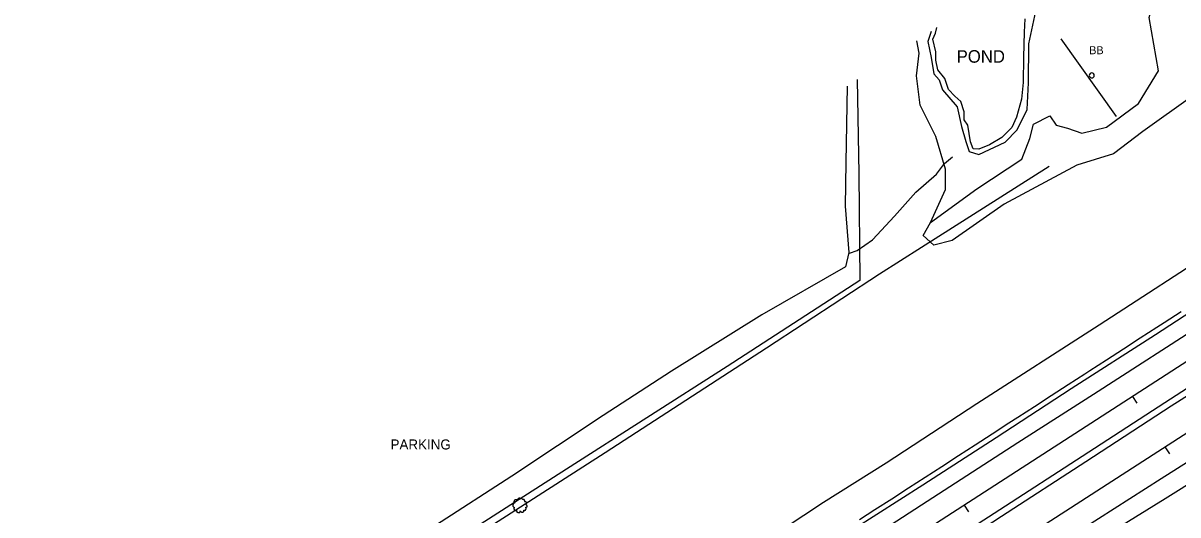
# Model space of a CAD drawing. Extents: x 1901471 to 1963503, y 756461 to 799997.
# Drawn here: x 1920585 to 1921162, y 767828 to 768073 of the extents above; entities that cross this region are included whole.
import ezdxf

# ---------------------------------------------------------------- set-up
doc = ezdxf.new("R2010")
doc.units = 0
for name, color, linetype in [('Default', 7, 'Continuous'), ('RD_DTM_BkLn1', 7, 'Continuous'), ('RD_EX_Bldg', 7, 'Continuous'), ('RD_EX_Fence_Other', 7, 'Continuous'), ('RD_EX_H2O', 7, 'Continuous'), ('RD_EX_Road', 7, 'Continuous'), ('RD_EX_VEG', 7, 'Continuous'), ('RD_HC_Cl', 7, 'Continuous'), ('RD_HC_Data_Tic', 7, 'Continuous')]:
    doc.layers.add(name, color=color, linetype=linetype)

# ---------------------------------------------------------------- blocks, each defined once
blk = doc.blocks.new('T2')
at = {"layer": 'RD_EX_VEG'}
for points in [[(0.05233333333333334, 7.213166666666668), (-0.24750000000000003, 7.238166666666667), (-0.5723333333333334, 7.138166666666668), (-0.8222500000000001, 7.038250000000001), (-1.0471666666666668, 6.963250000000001), (-1.2720833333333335, 6.863250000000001), (-1.5719166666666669, 6.688416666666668), (-1.7968333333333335, 6.488416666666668), (-1.9218333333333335, 6.2385833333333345), (-1.9718333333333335, 6.013666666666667), (-2.0217500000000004, 5.738833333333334), (-2.0217500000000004, 5.563833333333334), (-2.146666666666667, 5.538833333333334), (-2.296666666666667, 5.563833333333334), (-2.5465000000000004, 5.638833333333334), (-2.796416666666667, 5.638833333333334), (-3.0463333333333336, 5.638833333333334), (-3.3961666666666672, 5.613833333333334), (-3.7460000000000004, 5.613833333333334), (-4.020833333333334, 5.563833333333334), (-4.345750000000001, 5.513916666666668), (-4.720583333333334, 5.389000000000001), (-5.0704166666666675, 5.264000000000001), (-5.37025, 5.014083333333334), (-5.620166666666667, 4.539333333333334), (-5.745166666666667, 4.189500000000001), (-5.895083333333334, 3.9395833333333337), (-5.745166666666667, 3.489833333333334), (-5.570166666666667, 3.139916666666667), (-5.545250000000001, 2.9400000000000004), (-5.470250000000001, 2.5152500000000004), (-5.37025, 2.2903333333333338), (-5.245333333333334, 2.0903333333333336), (-5.320250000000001, 2.065416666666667), (-5.695166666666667, 2.015416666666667), (-5.995000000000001, 1.9155000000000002), (-6.419833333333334, 1.6905833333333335), (-6.644750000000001, 1.465666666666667), (-6.744750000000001, 1.1407500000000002), (-6.769666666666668, 0.7909166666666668), (-6.869583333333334, 0.5910833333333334), (-6.944583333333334, 0.3161666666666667), (-6.969583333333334, 0.2411666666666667), (-7.019583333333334, -0.08366666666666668), (-6.9195833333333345, -0.5335000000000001), (-6.894583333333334, -0.8833333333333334), (-6.769666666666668, -1.1082500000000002), (-6.619750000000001, -1.2830833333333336), (-6.444833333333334, -1.5330000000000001), (-6.045000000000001, -1.7579166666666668), (-5.7201666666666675, -1.8579166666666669), (-5.520250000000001, -1.8828333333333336), (-5.695166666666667, -2.382666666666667), (-5.745166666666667, -2.7325000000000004), (-5.870083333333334, -3.132333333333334), (-5.870083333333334, -3.2072500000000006), (-5.920000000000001, -3.682083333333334), (-5.770166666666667, -4.007000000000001), (-5.695166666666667, -4.38175), (-5.520250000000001, -4.606666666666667), (-5.245333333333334, -4.906583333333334), (-4.9205000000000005, -5.131416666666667), (-4.420666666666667, -5.256416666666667), (-4.020833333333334, -5.231416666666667), (-3.4460833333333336, -5.056500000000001), (-3.1962500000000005, -4.9815000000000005), (-3.2212500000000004, -5.156416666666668), (-3.1962500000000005, -5.531333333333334), (-3.1962500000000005, -5.956083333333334), (-3.0463333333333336, -6.280916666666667), (-2.946333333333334, -6.555833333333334), (-2.796416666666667, -6.805750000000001), (-2.4715000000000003, -7.030583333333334), (-2.07175, -7.1055833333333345), (-1.6469166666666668, -7.2555000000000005), (-1.1970833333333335, -7.330500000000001), (-0.6973333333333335, -7.355500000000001), (-0.09758333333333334, -7.205583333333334), (0.17725000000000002, -7.080583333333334), (0.27725000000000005, -6.905666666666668), (0.47716666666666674, -6.530833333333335), (0.4271666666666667, -6.3059166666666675), (0.4521666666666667, -5.706166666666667), (0.5520833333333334, -5.881166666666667), (0.7270833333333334, -6.231000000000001), (1.2268333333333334, -6.530833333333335), (1.626666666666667, -6.705750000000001), (2.101416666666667, -6.8557500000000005), (2.4013333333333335, -6.930666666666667), (2.8760833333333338, -6.8557500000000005), (3.2510000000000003, -6.780750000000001), (3.6257500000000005, -6.655750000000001), (3.9256666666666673, -6.380916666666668), (4.100583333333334, -6.106000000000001), (4.1505833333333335, -5.831166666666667), (4.2255, -5.456333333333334), (4.275500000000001, -5.281416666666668)], [(4.275500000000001, -5.281416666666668), (4.200583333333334, -5.106416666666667), (4.1505833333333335, -4.856583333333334), (4.2255, -4.881583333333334), (4.4004166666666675, -4.931583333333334), (4.675333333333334, -5.056500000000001), (4.900250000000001, -5.131416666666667), (5.225083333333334, -5.106416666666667), (5.500000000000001, -5.006500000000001), (5.949750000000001, -4.731583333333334), (6.224666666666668, -4.256833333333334), (6.499500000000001, -3.8570000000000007), (6.5745000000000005, -3.5321666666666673), (6.524500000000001, -3.3072500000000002), (6.499500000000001, -2.8075000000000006), (6.299583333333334, -2.5575833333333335), (6.249583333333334, -2.432666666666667), (6.1496666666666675, -2.0328333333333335), (6.224666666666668, -1.9828333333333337), (6.499500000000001, -1.9328333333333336), (6.874333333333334, -1.8079166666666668), (7.149250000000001, -1.6830000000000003), (7.374166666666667, -1.5080000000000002), (7.449083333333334, -1.2830833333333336), (7.424166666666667, -0.8833333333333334), (7.4740833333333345, -0.48350000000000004), (7.399166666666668, -0.3335), (7.299166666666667, -0.1836666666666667), (7.224166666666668, 0.016333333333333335), (7.074250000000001, 0.16616666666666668), (6.974333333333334, 0.3161666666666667), (6.874333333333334, 0.41608333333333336), (6.749416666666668, 0.5660833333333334), (6.5745000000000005, 0.6910000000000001), (6.424583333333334, 0.7410000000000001), (6.374583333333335, 0.8909166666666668), (6.524500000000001, 1.0908333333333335), (6.5745000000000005, 1.1907500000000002), (6.599416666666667, 1.4156666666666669), (6.824416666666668, 1.7655000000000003), (6.874333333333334, 2.1653333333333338), (6.824416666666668, 2.590166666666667), (6.774416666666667, 2.8650833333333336), (6.624416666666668, 3.139916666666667), (6.424583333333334, 3.3898333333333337), (6.299583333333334, 3.5647500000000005), (6.124666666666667, 3.689666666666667), (5.799833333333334, 3.814666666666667), (5.549916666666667, 3.864583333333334), (5.200083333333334, 3.864583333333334), (5.000166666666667, 3.9145833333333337), (5.025166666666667, 3.964583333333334), (5.025166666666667, 4.1145000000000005), (5.025166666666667, 4.389416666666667), (4.950166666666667, 4.839166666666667), (4.800250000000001, 5.339), (4.800250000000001, 5.364000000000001), (4.7002500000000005, 5.613833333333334), (4.475416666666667, 5.813750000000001), (4.3005, 5.913666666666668), (4.100583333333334, 6.038666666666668), (3.850666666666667, 6.063666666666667), (3.5508333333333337, 6.063666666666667), (3.2759166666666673, 6.013666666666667), (3.0760000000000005, 5.913666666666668), (2.9010833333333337, 5.788750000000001), (2.8260833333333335, 5.938666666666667), (2.726166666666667, 6.2385833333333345), (2.676166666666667, 6.3885000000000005), (2.52625, 6.563416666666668), (2.301416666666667, 6.7633333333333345), (1.8515000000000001, 6.888250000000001), (1.2268333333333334, 6.813333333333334), (0.9269166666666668, 6.613416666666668), (0.7770000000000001, 6.438500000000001), (0.7270833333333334, 6.563416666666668), (0.5270833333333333, 6.7633333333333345), (0.4271666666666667, 6.938250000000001), (0.25225000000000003, 7.063250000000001), (0.10233333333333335, 7.163166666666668), (0.0023333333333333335, 7.213166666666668)]]:
    blk.add_spline(points, degree=3, dxfattribs=at)
blk = doc.blocks.new('SIGNPOST')
at = {"layer": 'Default'}
for centre, start, end in [((7.776250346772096e-18, 0), 90.00000000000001, 270), ((-7.776250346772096e-18, 0), 270, 90)]:
    blk.add_arc(centre, 0.12700000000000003, start, end, dxfattribs=at)

msp = doc.modelspace()

# ---------------------------------------------------------------- linework, layer by layer
at = {"layer": 'RD_DTM_BkLn1'}
for points in [[(1921010.6918800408, 767830.4550401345), (1921019.0928901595, 767835.876703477), (1921027.493900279, 767841.2983668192), (1921035.8949103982, 767846.7200301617), (1921044.0662682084, 767851.9934854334), (1921052.462636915, 767857.4237984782), (1921060.8590056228, 767862.8541115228), (1921069.2553743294, 767868.2844245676), (1921077.651743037, 767873.7147376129), (1921082.014529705, 767876.5363499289), (1921090.405634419, 767881.9755113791), (1921098.7967391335, 767887.4146728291), (1921107.1878438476, 767892.8538342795), (1921115.5789485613, 767898.2929957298), (1921117.976496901, 767899.8471000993), (1921126.3686554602, 767905.2850721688), (1921134.7608140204, 767910.7230442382), (1921143.15297258, 767916.1610163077), (1921151.5451311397, 767921.5989883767), (1921155.1347027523, 767923.9249680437), (1921163.5709169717, 767929.292706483)], [(1921003.0432958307, 767825.4376232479), (1921010.6918800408, 767830.4550401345)]]:
    msp.add_lwpolyline(points, dxfattribs=at)
at = {"layer": 'RD_EX_Bldg'}
msp.add_lwpolyline([(1921103.6000000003, 768065.5900000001), (1921131.2100000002, 768026.7200000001)], dxfattribs=at)
at = {"layer": 'RD_EX_Fence_Other'}
for points in [[(1921001.9300000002, 768045.2100000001), (1921002.7200000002, 767998.1800000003), (1921003.1200000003, 767944.8600000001), (1920936.9200000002, 767901.9300000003), (1920856.7200000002, 767850.6400000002), (1920656.5500000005, 767722.32), (1920585.89, 767676.9300000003), (1920559.1900000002, 767759.08)], [(1920573.0200000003, 767668.2800000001), (1920657.6100000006, 767718.1000000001), (1920711.9000000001, 767752.1900000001), (1920797.9300000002, 767808.9300000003), (1920876.0700000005, 767858.9200000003), (1920956.5700000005, 767911.2900000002), (1921013.0500000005, 767948.1600000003), (1921034.0200000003, 767961.4200000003), (1921097.6700000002, 768002.0300000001)], [(1920490.14, 767425.3700000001), (1920534.7000000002, 767451.81), (1920585.6200000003, 767483.31), (1920625.7600000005, 767508.5200000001), (1920748.1500000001, 767583.4300000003), (1920802.5000000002, 767617.55), (1920866.9500000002, 767657.5300000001), (1920927.8100000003, 767695.0400000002), (1920985.3400000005, 767730.7200000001), (1921042.5200000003, 767766.4400000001), (1921095.0000000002, 767798.5900000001), (1921155.5900000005, 767836.0100000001), (1921208.9800000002, 767869.4500000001), (1921262.39, 767902.3400000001), (1921315.2400000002, 767935.2000000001), (1921371.9100000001, 767970.31), (1921406.2000000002, 767992.3600000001), (1921374.0100000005, 767974.7200000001)]]:
    msp.add_lwpolyline(points, dxfattribs=at)
at = {"layer": 'RD_EX_H2O'}
for points in [[(1921085.64, 768075.5900000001), (1921085.2900000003, 768068.8700000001), (1921084.9400000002, 768056.4600000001), (1921084.7100000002, 768043.6800000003), (1921083.9600000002, 768035.4500000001), (1921081.4000000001, 768026.3400000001), (1921079.1300000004, 768021.2800000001), (1921074.1600000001, 768016.32), (1921067.9600000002, 768012.6800000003), (1921062.6300000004, 768010.4700000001), (1921059.8300000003, 768010.6000000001), (1921058.4000000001, 768014.1500000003), (1921057.1300000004, 768022.3500000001), (1921055.3600000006, 768025.07), (1921055.3400000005, 768029.1600000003), (1921053.5900000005, 768034.2900000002), (1921050.64, 768036.9400000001), (1921047.4100000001, 768040.2500000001), (1921045.64, 768045.7800000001), (1921042.0900000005, 768050.08), (1921041.0600000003, 768054.8800000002), (1921041.1200000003, 768059.0300000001), (1921039.7000000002, 768065.3900000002), (1921041.0100000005, 768068.3900000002), (1921041.6800000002, 768071.1800000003)], [(1920997.9600000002, 767958.5100000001), (1921001.8500000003, 767959.8700000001), (1921009.5700000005, 767965.1400000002), (1921020.5800000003, 767977.0400000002), (1921031.1800000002, 767988.9300000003), (1921041.5200000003, 767997.9600000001), (1921045.4500000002, 768003.3400000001), (1921049.4700000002, 768006.6500000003)], [(1920293.3800000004, 767382.2500000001), (1920311.9600000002, 767394.3900000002), (1920362.7600000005, 767427.4600000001), (1920400.4800000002, 767450.7600000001), (1920554.2400000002, 767553.1000000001), (1920698.3700000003, 767648.2300000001), (1920735.3200000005, 767671.8), (1920780.3000000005, 767701.6600000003), (1920829.4100000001, 767733.8400000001), (1920869.9200000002, 767760.3600000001), (1920910.4900000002, 767786.0200000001), (1920955.5500000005, 767814.7000000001), (1920985.0400000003, 767834.2200000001), (1921016.3600000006, 767853.82), (1921061.6200000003, 767883.3600000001), (1921122.7400000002, 767922.6600000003), (1921184.7200000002, 767963.07)], [(1920619.2200000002, 767506.4800000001), (1920747.5400000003, 767585.6500000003), (1920790.2800000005, 767612.0100000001), (1920837.9600000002, 767643.7800000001), (1920883.6000000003, 767672.81), (1920929.9700000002, 767702.8800000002), (1920978.9200000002, 767734.7100000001), (1921020.6900000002, 767760.5400000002), (1921062.1200000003, 767787.7000000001), (1921106.64, 767816.05), (1921153.7200000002, 767845.9000000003), (1921209.4700000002, 767881.3)]]:
    msp.add_lwpolyline(points, dxfattribs=at)
at = {"layer": 'RD_EX_Road'}
for points in [[(1920996.8000000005, 768041.8600000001), (1920996.1800000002, 768003.83), (1920995.89, 767982.0200000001), (1920997.7700000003, 767958.8), (1920995.9800000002, 767951.6000000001), (1920954.2000000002, 767927.6300000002), (1920909.1900000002, 767899.55), (1920874.9900000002, 767877.3600000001), (1920829.3800000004, 767847.1100000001), (1920791.3400000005, 767822.4600000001), (1920738.5100000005, 767787.3400000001), (1920688.0200000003, 767754.4700000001), (1920652.3500000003, 767732.83), (1920601.6800000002, 767699.9700000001), (1920595.5600000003, 767698.08), (1920591.1300000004, 767699.7600000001), (1920585.4400000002, 767707.1500000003), (1920564.3600000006, 767762.4600000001)], [(1921197.0400000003, 767947.8400000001), (1921150.7400000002, 767917.6500000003), (1921108.6800000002, 767890.7100000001), (1921071.2400000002, 767866.3500000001), (1921034.5700000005, 767842.6600000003), (1921000.1800000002, 767820.7200000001), (1920962.0000000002, 767795.6600000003), (1920923.3100000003, 767770.8900000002), (1920887.6100000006, 767747.8500000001), (1920853.9900000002, 767726.1800000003), (1920817.0700000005, 767702.3500000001), (1920780.8600000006, 767679.2800000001), (1920741.64, 767654.1300000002), (1920714.2600000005, 767636.7400000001), (1920677.2300000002, 767612.6900000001), (1920629.0200000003, 767581.1600000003), (1920585.9100000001, 767554.4300000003), (1920495.2600000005, 767495.1500000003), (1920374.4800000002, 767417.3500000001), (1920308.3400000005, 767374.6100000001)], [(1921178.2000000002, 767925.5900000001), (1921119.8100000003, 767887.9500000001), (1921082.0600000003, 767863.8400000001), (1921034.0200000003, 767832.7100000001), (1920984.2300000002, 767800.3500000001), (1920930.7600000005, 767765.9300000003), (1920883.4800000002, 767735.4200000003), (1920842.0900000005, 767708.7700000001), (1920796.9800000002, 767679.81), (1920755.0100000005, 767653.05), (1920719.6300000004, 767629.9900000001), (1920652.14, 767586.2200000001), (1920620.8100000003, 767565.9700000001), (1920594.7600000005, 767549.5200000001), (1920545.6200000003, 767518.06), (1920440.0900000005, 767449.4300000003), (1920363.9300000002, 767400.3800000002), (1920317.3100000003, 767370.0200000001)], [(1920341.1500000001, 767357.83), (1920343.9800000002, 767359.6700000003), (1920451.1500000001, 767429.0300000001), (1920532.2000000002, 767482.07), (1920608.5400000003, 767531.2100000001), (1920635.2500000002, 767547.9300000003), (1920675.4300000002, 767574.2000000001), (1920731.5600000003, 767610.2300000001), (1920766.5500000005, 767632.7800000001), (1920813.6100000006, 767663.1100000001), (1920855.5800000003, 767690.1300000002), (1920899.6200000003, 767718.4600000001), (1920941.3300000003, 767745.31), (1920984.6300000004, 767773.1400000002), (1921029.2700000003, 767802.2600000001), (1921073.0500000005, 767830.55), (1921114.2600000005, 767857.1700000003), (1921155.4300000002, 767883.8900000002), (1921196.1200000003, 767910.2200000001)], [(1920344.2800000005, 767356.2300000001), (1920347.1200000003, 767358.07), (1920394.1100000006, 767388.4700000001), (1920503.5500000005, 767459.3600000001), (1920610.2300000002, 767528.4600000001), (1920650.6500000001, 767554.3700000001), (1920685.8700000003, 767576.31), (1920733.4100000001, 767607.4400000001), (1920775.64, 767634.3600000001), (1920808.8100000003, 767655.7100000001), (1920842.4200000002, 767677.5300000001), (1920879.7800000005, 767701.56), (1920917.1800000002, 767725.8600000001), (1920955.1500000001, 767750.2200000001), (1920992.8800000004, 767774.7700000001), (1921031.0800000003, 767799.2800000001), (1921073.9600000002, 767827.2500000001), (1921115.9800000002, 767854.4600000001), (1921158.6100000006, 767882.2400000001), (1921202.8100000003, 767910.31)]]:
    msp.add_lwpolyline(points, dxfattribs=at)
at = {"layer": 'RD_EX_VEG'}
for points in [[(1921169.4400000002, 768037.0300000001), (1921144.5100000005, 768019.3), (1921129.8100000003, 768008.1400000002), (1921111.5900000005, 768002.5300000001), (1921075.2500000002, 767983.0000000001), (1921049.3400000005, 767964.8900000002), (1921040.1000000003, 767962.4900000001), (1921034.8700000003, 767967.3800000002), (1921038.5000000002, 767973.8600000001), (1921061.5300000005, 767990.58), (1921084.1200000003, 768005.4100000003), (1921088.1300000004, 768015.7000000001), (1921089.9600000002, 768022.8500000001), (1921098.0300000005, 768027.1300000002), (1921101.2900000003, 768022.4000000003), (1921106.8800000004, 768020.9900000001), (1921114.0000000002, 768018.4200000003), (1921126.3300000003, 768021.3500000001), (1921142.4000000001, 768033.1900000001), (1921152.2500000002, 768049.5400000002), (1921147.6000000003, 768076.1600000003), (1921152.7900000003, 768095.9700000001), (1921169.7200000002, 768121.7500000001)], [(1921038.7300000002, 768069.2500000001), (1921037.2200000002, 768064.2000000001), (1921038.8600000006, 768056.1400000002), (1921040.1000000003, 768048.08), (1921042.8700000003, 768045.06), (1921044.4800000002, 768040.1000000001), (1921051.7600000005, 768031.5300000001), (1921054.0200000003, 768021.82), (1921056.1800000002, 768014.2500000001), (1921057.8500000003, 768009.32), (1921062.5800000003, 768007.7600000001), (1921075.8300000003, 768013.9400000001), (1921081.8200000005, 768020.1000000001), (1921086.6800000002, 768030.31), (1921087.3300000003, 768043.6200000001), (1921087.5400000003, 768063.05), (1921091.0400000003, 768079.2700000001), (1921085.9400000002, 768088.6900000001), (1921081.1700000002, 768094.4000000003), (1921079.39, 768095.81)], [(1921038.5000000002, 767973.8600000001), (1921045.9400000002, 767990.32), (1921046.0400000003, 768000.4400000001), (1921041.1000000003, 768016.83), (1921033.3600000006, 768032.4600000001), (1921031.4900000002, 768047.08), (1921032.7700000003, 768058.33), (1921031.5700000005, 768064.57)]]:
    msp.add_lwpolyline(points, dxfattribs=at)
at = {"layer": 'RD_HC_Cl'}
for p, q in [((1926729.5176193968, 771495.9286460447), (1917217.2707724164, 765354.9153898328)), ((1926745.7566169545, 771470.7766377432), (1917232.2344163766, 765328.8252854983))]:
    msp.add_line(p, q, dxfattribs=at)
at = {"layer": 'RD_HC_Data_Tic'}
for p, q in [((1921139.2762247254, 767886.9236378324), (1921141.445749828, 767883.5631079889)), ((1921155.5459448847, 767861.7240415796), (1921157.715498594, 767858.3635302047)), ((1921055.2629786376, 767832.685510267), (1921057.4325037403, 767829.3249804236))]:
    msp.add_line(p, q, dxfattribs=at)

# ---------------------------------------------------------------- block references
at = {"layer": 'RD_EX_Bldg', "xscale": 9.84251968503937, "yscale": 9.84251968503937}
msp.add_blockref('SIGNPOST', (1921119.0200000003, 768047.2900000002), dxfattribs=at)
at = {"layer": 'RD_EX_VEG', "xscale": 0.4921259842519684, "yscale": 0.4921259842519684}
msp.add_blockref('T2', (1920833.39, 767832.5900000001), dxfattribs=at)

# ---------------------------------------------------------------- texts
at = {"layer": 'RD_EX_H2O'}
msp.add_text('POND', height=6.250000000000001, dxfattribs=at).set_placement((1921051.5100000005, 768053.6200000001))
at = {"layer": 'RD_EX_Road'}
for s, height, p in [('BB', 4.000000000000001, (1921117.7500000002, 768057.8500000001)), ('PARKING', 5.000000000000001, (1920768.9000000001, 767860.4800000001))]:
    msp.add_text(s, height=height, dxfattribs=at).set_placement(p)

doc.saveas('drawing.dxf')
